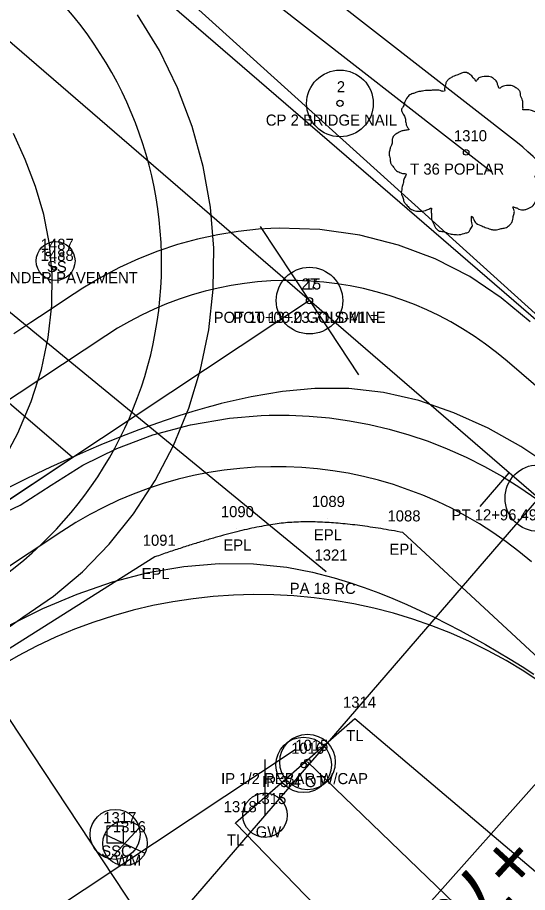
# Model space of a CAD drawing. Extents: x 1812113 to 1819860, y 1177290 to 1181185.
# Drawn here: x 1813803.6 to 1813849.5, y 1178588.3 to 1178667.1 of the extents above; entities that cross this region are included whole.
import ezdxf

# ---------------------------------------------------------------- set-up
doc = ezdxf.new("R2010")
doc.units = 0
for name, color, linetype in [('RD_EX_DR_Inlet', 7, 'Continuous'), ('RD_EX_DR_Pipe', 7, 'Continuous'), ('RD_EX_DR_Pipe_txCode', 7, 'Continuous'), ('RD_EX_DV_Prop', 7, 'Continuous'), ('RD_EX_DV_Prop_txCode', 7, 'Continuous'), ('RD_EX_DV_PropPin', 7, 'Continuous'), ('RD_EX_Road', 7, 'Continuous'), ('RD_EX_Road_txCode', 7, 'Continuous'), ('RD_EX_RW', 7, 'Continuous'), ('RD_EX_UT', 7, 'Continuous'), ('RD_EX_UT_txCode', 7, 'Continuous'), ('RD_EX_VEG', 7, 'Continuous'), ('RD_EX_VEG_txCode', 7, 'Continuous'), ('RD_HC_CL', 7, 'Continuous'), ('RD_HC_Data', 7, 'Continuous'), ('RD_HC_Data_Tic', 7, 'Continuous'), ('RD_HC_txCode', 7, 'Continuous'), ('RD_PD_ALT1_TrvlWay', 7, 'Continuous'), ('RD_PD_ALT3_TnTmp', 7, 'Continuous'), ('RD_PD_Final_TnTmp', 7, 'Continuous'), ('RD_PD_GR', 7, 'Continuous'), ('RD_PD_PatLn1', 7, 'Continuous'), ('RD_Sketch10', 7, 'Continuous'), ('RD_Sketch6', 7, 'Continuous'), ('RD_Sketch7', 7, 'Continuous'), ('RD_SMD_Locator', 7, 'Continuous')]:
    doc.layers.add(name, color=color, linetype=linetype)

msp = doc.modelspace()

# ---------------------------------------------------------------- linework, layer by layer
at = {"layer": 'RD_EX_DR_Inlet'}
for centre, radius in [((1813807.047, 1178645.143), 1.75), ((1813806.382, 1178645.773), 0.175), ((1813807.607, 1178645.703), 0.175), ((1813806.959, 1178644.478), 0.175)]:
    msp.add_circle(centre, radius, dxfattribs=at)
at = {"layer": 'RD_EX_DR_Pipe'}
msp.add_line((1813831.42, 1178617.18), (1813794.721, 1178647.236), dxfattribs=at)
at = {"layer": 'RD_EX_DV_Prop'}
for p, q in [((1813747.534, 1178587.015), (1813808.574, 1178627.442)), ((1814007.156, 1178429.487), (1813829.727, 1178600.057))]:
    msp.add_line(p, q, dxfattribs=at)
at = {"layer": 'RD_EX_DV_PropPin'}
for centre, radius in [((1813829.382, 1178599.79), 2.499), ((1813829.727, 1178600.057), 2.499), ((1813829.727, 1178600.057), 0.25), ((1813829.382, 1178599.79), 0.25)]:
    msp.add_circle(centre, radius, dxfattribs=at)
at = {"layer": 'RD_EX_Road'}
for p, q in [((1813875.667, 1178586.101), (1813838.317, 1178620.701)), ((1813815.993, 1178618.513), (1813795.139, 1178605.391))]:
    msp.add_line(p, q, dxfattribs=at)
msp.add_lwpolyline([(1814076.449, 1178427.399), (1814038.861, 1178461.867), (1814001.829, 1178496.617), (1813965.148, 1178531.537), (1813928.085, 1178567.095), (1813892.01, 1178601.225), (1813854.538, 1178636.515), (1813817.438, 1178670.033), (1813779.867, 1178701.638)], dxfattribs=at)
msp.add_open_spline([(1813838.317, 1178620.701), (1813831.507, 1178622.001), (1813823.352, 1178621.085), (1813815.993, 1178618.513)], degree=2, dxfattribs=at)
at = {"layer": 'RD_EX_RW'}
for p, q in [((1813808.574, 1178627.442), (1813739.051, 1178686.932)), ((1813828.61, 1178601.131), (1813762.676, 1178557.462))]:
    msp.add_line(p, q, dxfattribs=at)
at = {"layer": 'RD_EX_UT'}
for p, q in [((1813825.906, 1178595.263), (1813825.906, 1178600.263)), ((1813813.153, 1178594.288), (1813811.653, 1178594.288)), ((1813811.653, 1178594.288), (1813811.653, 1178592.788)), ((1813811.936, 1178591.267), (1813814.604, 1178594.163)), ((1813813.153, 1178592.788), (1813813.153, 1178594.288)), ((1813811.455, 1178593.562), (1813815.086, 1178591.849)), ((1813811.653, 1178592.788), (1813813.153, 1178592.788))]:
    msp.add_line(p, q, dxfattribs=at)
for centre, radius in [((1813825.906, 1178595.263), 1.999), ((1813812.403, 1178593.538), 2.25), ((1813813.288, 1178592.725), 2)]:
    msp.add_circle(centre, radius, dxfattribs=at)
at = {"layer": 'RD_EX_VEG'}
msp.add_lwpolyline([(1813964.655, 1178448.478), (1813984.607, 1178463.547), (1813943.712, 1178503.461), (1813904.65, 1178537.574), (1813863.787, 1178578.715), (1813833.989, 1178603.935), (1813823.244, 1178594.531), (1813964.655, 1178448.478)], dxfattribs=at)
for centre, radius in [((1813844.018, 1178654.917), 0.25), ((1813844.005, 1178654.898), 0.0001)]:
    msp.add_circle(centre, radius, dxfattribs=at)
for points in [[(1813844.15, 1178662.084), (1813843.85, 1178662.109), (1813843.525, 1178662.009), (1813843.275, 1178661.909), (1813843.05, 1178661.834), (1813842.826, 1178661.734), (1813842.526, 1178661.559), (1813842.301, 1178661.359), (1813842.176, 1178661.11), (1813842.126, 1178660.885), (1813842.076, 1178660.61), (1813842.076, 1178660.435), (1813841.951, 1178660.41), (1813841.801, 1178660.435), (1813841.551, 1178660.51), (1813841.301, 1178660.51), (1813841.051, 1178660.51), (1813840.701, 1178660.485), (1813840.352, 1178660.485), (1813840.077, 1178660.435), (1813839.752, 1178660.385), (1813839.377, 1178660.26), (1813839.027, 1178660.135), (1813838.727, 1178659.885), (1813838.477, 1178659.41), (1813838.352, 1178659.06), (1813838.203, 1178658.811), (1813838.352, 1178658.361), (1813838.527, 1178658.011), (1813838.552, 1178657.811), (1813838.627, 1178657.386), (1813838.727, 1178657.161), (1813838.852, 1178656.961), (1813838.777, 1178656.936), (1813838.402, 1178656.886), (1813838.103, 1178656.786), (1813837.678, 1178656.562), (1813837.453, 1178656.337), (1813837.353, 1178656.012), (1813837.328, 1178655.662), (1813837.228, 1178655.462), (1813837.153, 1178655.187), (1813837.128, 1178655.112), (1813837.078, 1178654.787), (1813837.178, 1178654.337), (1813837.203, 1178653.988), (1813837.328, 1178653.763), (1813837.478, 1178653.588), (1813837.653, 1178653.338), (1813838.053, 1178653.113), (1813838.377, 1178653.013), (1813838.577, 1178652.988), (1813838.402, 1178652.488), (1813838.352, 1178652.138), (1813838.228, 1178651.739), (1813838.228, 1178651.664), (1813838.178, 1178651.189), (1813838.327, 1178650.864), (1813838.402, 1178650.489), (1813838.577, 1178650.264), (1813838.852, 1178649.964), (1813839.177, 1178649.74), (1813839.677, 1178649.615), (1813840.077, 1178649.64), (1813840.652, 1178649.814), (1813840.901, 1178649.889), (1813840.876, 1178649.715), (1813840.901, 1178649.34), (1813840.901, 1178648.915), (1813841.051, 1178648.59), (1813841.151, 1178648.315), (1813841.301, 1178648.065), (1813841.626, 1178647.84), (1813842.026, 1178647.765), (1813842.451, 1178647.615), (1813842.901, 1178647.54), (1813843.4, 1178647.515), (1813844, 1178647.665), (1813844.275, 1178647.79), (1813844.375, 1178647.965), (1813844.575, 1178648.34), (1813844.525, 1178648.565), (1813844.55, 1178649.165), (1813844.65, 1178648.99), (1813844.825, 1178648.64), (1813845.324, 1178648.34), (1813845.724, 1178648.165), (1813846.199, 1178648.015), (1813846.499, 1178647.94), (1813846.974, 1178648.015), (1813847.349, 1178648.09), (1813847.723, 1178648.215), (1813848.023, 1178648.49), (1813848.198, 1178648.765), (1813848.248, 1178649.04), (1813848.323, 1178649.415), (1813848.373, 1178649.59)], [(1813848.373, 1178649.59), (1813848.298, 1178649.765), (1813848.248, 1178650.014), (1813848.323, 1178649.989), (1813848.498, 1178649.939), (1813848.773, 1178649.814), (1813848.998, 1178649.74), (1813849.323, 1178649.765), (1813849.598, 1178649.864), (1813850.047, 1178650.139), (1813850.322, 1178650.614), (1813850.597, 1178651.014), (1813850.672, 1178651.339), (1813850.622, 1178651.564), (1813850.597, 1178652.063), (1813850.397, 1178652.313), (1813850.347, 1178652.438), (1813850.247, 1178652.838), (1813850.322, 1178652.888), (1813850.597, 1178652.938), (1813850.972, 1178653.063), (1813851.247, 1178653.188), (1813851.472, 1178653.363), (1813851.547, 1178653.588), (1813851.522, 1178653.988), (1813851.572, 1178654.387), (1813851.497, 1178654.537), (1813851.397, 1178654.687), (1813851.322, 1178654.887), (1813851.172, 1178655.037), (1813851.072, 1178655.187), (1813850.972, 1178655.287), (1813850.847, 1178655.437), (1813850.672, 1178655.562), (1813850.522, 1178655.612), (1813850.472, 1178655.762), (1813850.622, 1178655.962), (1813850.672, 1178656.062), (1813850.697, 1178656.287), (1813850.922, 1178656.636), (1813850.972, 1178657.036), (1813850.922, 1178657.461), (1813850.872, 1178657.736), (1813850.722, 1178658.011), (1813850.522, 1178658.261), (1813850.397, 1178658.436), (1813850.222, 1178658.561), (1813849.897, 1178658.686), (1813849.648, 1178658.736), (1813849.298, 1178658.736), (1813849.098, 1178658.786), (1813849.123, 1178658.836), (1813849.123, 1178658.985), (1813849.123, 1178659.26), (1813849.048, 1178659.71), (1813848.898, 1178660.21), (1813848.898, 1178660.235), (1813848.798, 1178660.485), (1813848.573, 1178660.685), (1813848.398, 1178660.785), (1813848.198, 1178660.91), (1813847.948, 1178660.935), (1813847.648, 1178660.935), (1813847.374, 1178660.885), (1813847.174, 1178660.785), (1813846.999, 1178660.66), (1813846.924, 1178660.81), (1813846.824, 1178661.11), (1813846.774, 1178661.259), (1813846.624, 1178661.434), (1813846.399, 1178661.634), (1813845.949, 1178661.759), (1813845.324, 1178661.684), (1813845.025, 1178661.484), (1813844.875, 1178661.309), (1813844.825, 1178661.434), (1813844.625, 1178661.634), (1813844.525, 1178661.809), (1813844.35, 1178661.934), (1813844.2, 1178662.034), (1813844.1, 1178662.084)]]:
    msp.add_spline(points, degree=3, dxfattribs=at)
at = {"layer": 'RD_HC_CL'}
for p, q in [((1813850.516, 1178623.797), (1813755.38, 1178705.862)), ((1813829.909, 1178641.573), (1813743.828, 1178584.56))]:
    msp.add_line(p, q, dxfattribs=at)
at = {"layer": 'RD_HC_Data'}
msp.add_line((1813850.516, 1178623.797), (1813773.782, 1178534.841), dxfattribs=at)
for centre, radius in [((1813832.652, 1178659.325), 3), ((1813832.652, 1178659.325), 0.282), ((1813829.909, 1178641.573), 3), ((1813829.909, 1178641.573), 3), ((1813829.909, 1178641.573), 0.282), ((1813829.909, 1178641.573), 0.282), ((1813850.516, 1178623.797), 3)]:
    msp.add_circle(centre, radius, dxfattribs=at)
at = {"layer": 'RD_HC_Data_Tic'}
for p, q in [((1813829.909, 1178641.573), (1813825.492, 1178648.242)), ((1813829.909, 1178641.573), (1813834.327, 1178634.903)), ((1813847.862, 1178626.086), (1813845.25, 1178623.057))]:
    msp.add_line(p, q, dxfattribs=at)
at = {"layer": 'RD_PD_ALT1_TrvlWay'}
msp.add_line((1813855.7, 1178635.172), (1813779.98, 1178700.49), dxfattribs=at)
msp.add_arc((1813825.256, 1178570.123), 45, 48.20181, 123.51678, dxfattribs=at)
at = {"layer": 'RD_PD_Final_TnTmp'}
for q in [(1813800.408, 1178607.64), (1813855.249, 1178603.67)]:
    msp.add_line((1813825.286, 1178570.078), q, dxfattribs=at)
at = {"layer": 'RD_PD_GR'}
msp.add_line((1813806.909, 1178683.864), (1813846.352, 1178653.136), dxfattribs=at)
at = {"layer": 'RD_PD_PatLn1'}
msp.add_line((1813848.639, 1178655.787), (1813809.195, 1178686.515), dxfattribs=at)
msp.add_arc((1813200.515, 1177920.539), 980.129, 48.019126, 48.60371, dxfattribs=at)
at = {"layer": 'RD_Sketch10'}
msp.add_line((1813807.615, 1178620.81), (1813792.784, 1178610.987), dxfattribs=at)
for points in [[(1813762.812, 1178595.935), (1813765.797, 1178597.911), (1813768.782, 1178599.888), (1813771.767, 1178601.865), (1813774.751, 1178603.842), (1813777.736, 1178605.819), (1813780.681, 1178607.857), (1813783.559, 1178610.001), (1813786.42, 1178612.195), (1813789.329, 1178614.339), (1813792.27, 1178616.474), (1813792.27, 1178616.474), (1813795.1, 1178618.376), (1813797.989, 1178620.158), (1813800.912, 1178621.791), (1813803.844, 1178623.168), (1813806.651, 1178624.969), (1813809.502, 1178626.753), (1813812.56, 1178628.27), (1813815.803, 1178629.493), (1813819.194, 1178630.407), (1813822.695, 1178631), (1813825.552, 1178631.236)], [(1813825.552, 1178631.236), (1813826.272, 1178631.262), (1813828.077, 1178631.266), (1813829.886, 1178631.185), (1813831.696, 1178631.019), (1813833.502, 1178630.768), (1813835.299, 1178630.431), (1813837.084, 1178630.009), (1813838.851, 1178629.503), (1813840.596, 1178628.914), (1813842.315, 1178628.242), (1813844.005, 1178627.488), (1813845.66, 1178626.655), (1813847.276, 1178625.744), (1813848.851, 1178624.756), (1813850.379, 1178623.693)], [(1813767.23, 1178589.265), (1813770.215, 1178591.242), (1813773.199, 1178593.218), (1813776.184, 1178595.195), (1813779.169, 1178597.172), (1813782.154, 1178599.149), (1813785.138, 1178601.126), (1813788.123, 1178603.102), (1813791.108, 1178605.079), (1813794.095, 1178607.053), (1813797.105, 1178608.991), (1813797.105, 1178608.991), (1813797.105, 1178608.991), (1813799.972, 1178610.734), (1813802.903, 1178612.369), (1813805.909, 1178613.859), (1813808.997, 1178615.169), (1813812.168, 1178616.263), (1813815.39, 1178617.103), (1813818.6, 1178617.659), (1813821.767, 1178617.92), (1813824.863, 1178617.889), (1813827.861, 1178617.574), (1813830.176, 1178617.128)], [(1813830.176, 1178617.128), (1813830.742, 1178616.994), (1813832.137, 1178616.623), (1813833.502, 1178616.209), (1813834.837, 1178615.757), (1813836.145, 1178615.273), (1813837.426, 1178614.76), (1813838.682, 1178614.222), (1813839.914, 1178613.662), (1813841.123, 1178613.083), (1813842.311, 1178612.487), (1813843.478, 1178611.876), (1813844.626, 1178611.251), (1813845.756, 1178610.613), (1813846.869, 1178609.965), (1813847.965, 1178609.307), (1813849.047, 1178608.64), (1813850.115, 1178607.964)]]:
    msp.add_lwpolyline(points, dxfattribs=at)
msp.add_arc((1813826.942, 1178591.63), 35, 49.02058, 123.51678, dxfattribs=at)
at = {"layer": 'RD_Sketch6'}
for p, q in [((1813811.555, 1178638.412), (1813765.504, 1178607.912)), ((1813855.415, 1178629.476), (1813847.716, 1178636.117))]:
    msp.add_line(p, q, dxfattribs=at)
for points in [[(1813826.429, 1178648.062), (1813825.323, 1178647.994), (1813823.482, 1178647.8), (1813821.648, 1178647.506), (1813819.827, 1178647.112), (1813818.026, 1178646.618), (1813816.249, 1178646.025), (1813814.504, 1178645.335), (1813812.795, 1178644.549), (1813811.128, 1178643.67), (1813809.509, 1178642.699), (1813807.932, 1178641.669), (1813806.372, 1178640.637), (1813804.828, 1178639.606), (1813803.297, 1178638.576)], [(1813849.782, 1178639.662), (1813847.18, 1178641.831), (1813844.331, 1178643.736), (1813841.225, 1178645.327), (1813837.908, 1178646.578), (1813834.427, 1178647.466), (1813830.831, 1178647.973), (1813827.166, 1178648.087), (1813826.429, 1178648.062)], [(1813851.729, 1178626.596), (1813848.932, 1178628.436), (1813845.989, 1178630.088), (1813842.917, 1178631.488), (1813839.751, 1178632.578), (1813836.58, 1178633.308), (1813833.447, 1178633.669), (1813830.397, 1178633.671), (1813827.463, 1178633.396), (1813824.652, 1178632.924), (1813821.963, 1178632.31), (1813821.439, 1178632.174)], [(1813821.439, 1178632.174), (1813820.662, 1178631.962), (1813819.388, 1178631.592), (1813818.139, 1178631.202), (1813816.916, 1178630.797), (1813815.715, 1178630.376), (1813814.537, 1178629.944), (1813813.379, 1178629.5), (1813812.241, 1178629.048), (1813811.122, 1178628.587), (1813810.02, 1178628.118), (1813808.917, 1178627.636), (1813807.775, 1178627.123), (1813806.596, 1178626.58), (1813805.387, 1178626.008), (1813804.15, 1178625.41), (1813802.89, 1178624.787)]]:
    msp.add_lwpolyline(points, dxfattribs=at)
msp.add_arc((1813828.121, 1178613.401), 30, 49.21843, 123.51678, dxfattribs=at)
at = {"layer": 'RD_Sketch7'}
for points in [[(1813801.386, 1178611.185), (1813804.095, 1178613.081), (1813806.856, 1178614.986), (1813809.463, 1178617.18), (1813811.876, 1178619.661), (1813814.064, 1178622.401), (1813816.003, 1178625.372), (1813817.668, 1178628.543), (1813819.038, 1178631.885), (1813820.097, 1178635.365), (1813820.83, 1178638.949), (1813821.226, 1178642.605), (1813821.279, 1178646.297), (1813820.984, 1178649.991), (1813820.343, 1178653.652), (1813819.357, 1178657.247), (1813818.035, 1178660.741), (1813816.387, 1178664.101), (1813814.425, 1178667.296)], [(1813802.137, 1178626.839), (1813803.643, 1178629.647), (1813804.853, 1178632.505), (1813805.762, 1178635.387), (1813806.373, 1178638.269), (1813806.691, 1178641.125), (1813806.726, 1178643.933), (1813806.487, 1178646.672), (1813805.988, 1178649.319), (1813805.248, 1178651.86), (1813804.319, 1178654.292), (1813803.247, 1178656.623)]]:
    msp.add_lwpolyline(points, dxfattribs=at)
msp.add_arc((1813781.591, 1178644.954), 35, 303.51678, 49.21843, dxfattribs=at)
at = {"layer": 'RD_SMD_Locator'}
for centre in [(1813832.652, 1178659.325), (1813807.047, 1178645.143), (1813829.909, 1178641.573), (1813829.909, 1178641.573), (1813831.507, 1178622.001), (1813823.352, 1178621.085), (1813838.317, 1178620.701), (1813815.993, 1178618.513), (1813831.42, 1178617.18), (1813833.989, 1178603.935), (1813823.244, 1178594.531)]:
    msp.add_circle(centre, 0.001, dxfattribs=at)

# ---------------------------------------------------------------- texts
at = {"layer": 'RD_EX_DR_Pipe_txCode'}
for s, p in [('1321', (1813830.357, 1178618.18)), ('PA 18 RC', (1813828.128, 1178615.18))]:
    msp.add_text(s, height=1, dxfattribs=at).set_placement(p)
at = {"layer": 'RD_EX_DV_Prop_txCode'}
for s, p in [('1016', (1813828.256, 1178600.79)), ('1015', (1813828.625, 1178601.057)), ('IP 1/2 REBAR W/CAP', (1813821.948, 1178598.057)), ('IP 3/4 OT', (1813825.626, 1178597.79))]:
    msp.add_text(s, height=1, dxfattribs=at).set_placement(p)
at = {"layer": 'RD_EX_Road_txCode'}
for s, p in [('1089', (1813830.121, 1178623.001)), ('1090', (1813821.927, 1178622.085)), ('1088', (1813836.931, 1178621.701)), ('EPL', (1813830.303, 1178620.001)), ('1091', (1813814.89, 1178619.513)), ('EPL', (1813822.147, 1178619.085)), ('EPL', (1813837.112, 1178618.701)), ('EPL', (1813814.788, 1178616.513))]:
    msp.add_text(s, height=1, dxfattribs=at).set_placement(p)
at = {"layer": 'RD_EX_UT_txCode'}
for s, p in [('1487', (1813805.7, 1178646.143)), ('1488', (1813805.7, 1178645.143)), ('SS', (1813806.267, 1178644.143)), ('MHS UNDER PAVEMENT', (1813798.622, 1178643.143)), ('1315', (1813824.843, 1178596.263)), ('1317', (1813811.34, 1178594.538)), ('1316', (1813812.202, 1178593.725)), ('GW', (1813825.064, 1178593.263)), ('SSC', (1813811.151, 1178591.538)), ('WM', (1813812.383, 1178590.725))]:
    msp.add_text(s, height=1, dxfattribs=at).set_placement(p)
at = {"layer": 'RD_EX_VEG_txCode'}
for s, p in [('1310', (1813842.916, 1178655.917)), ('T 36 POPLAR', (1813838.971, 1178652.917)), ('1314', (1813832.926, 1178604.935)), ('TL', (1813833.217, 1178601.935)), ('1318', (1813822.181, 1178595.531)), ('TL', (1813822.472, 1178592.531))]:
    msp.add_text(s, height=1, dxfattribs=at).set_placement(p)
at = {"layer": 'RD_HC_txCode'}
for s, p in [('2', (1813832.369, 1178660.325)), ('CP 2 BRIDGE NAIL', (1813825.975, 1178657.325)), ('27', (1813829.177, 1178642.573)), ('15', (1813829.46, 1178642.573)), ('POT 10+00.0 GOLDMINE', (1813821.275, 1178639.573)), ('POT 13+23.71 S-41 =', (1813823.043, 1178639.573)), ('PT 12+96.49 RD S-41', (1813842.705, 1178621.797))]:
    msp.add_text(s, height=1, dxfattribs=at).set_placement(p)
at = {"layer": 'RD_PD_ALT3_TnTmp'}
msp.add_text('+79.55', height=5, rotation=227.45205, dxfattribs=at).set_placement((1813847.434, 1178594.097))

doc.saveas('drawing.dxf')
